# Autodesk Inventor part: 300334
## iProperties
Created: 2007-11
Part Number: 300334
Document SubType Name: Modeling
Designer: TH
Density: 7.85 g/cm^3
Mass: 603.841 g
Surface Area: 1574.23 cm^2
Volume: 76.9224 cm^3
Material: Steel
Description: RIGHT SIDE BACK MEMBER
Component Category: Back Component
Author: TH
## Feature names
1. Extrusion1
2. Fillet1
3. Extrusion2
4. Extrusion3
5. Fillet2
6. Fillet3
7. Fillet4
8. Fillet5
9. Fillet6
10. Extrusion4
11. Fillet7
12. Fillet10
13. Fillet11
14. Fillet13
15. Fillet14
16. Extrusion5
17. Revolution1
18. Fillet15
19. Shell1
20. Extrusion6
21. Extrusion7
22. Fillet16
23. Fillet17
24. Fillet18
25. Extrusion8
26. Hole1
